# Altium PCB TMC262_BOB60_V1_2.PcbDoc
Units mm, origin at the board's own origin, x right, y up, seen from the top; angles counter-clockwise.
Board outline 38.1 x 30.48 mm, 4 copper layers (Top, GND, VM, Bottom), stack 0.704 mm thick; 33 components, 31 nets, 107 pads, 150 vias.
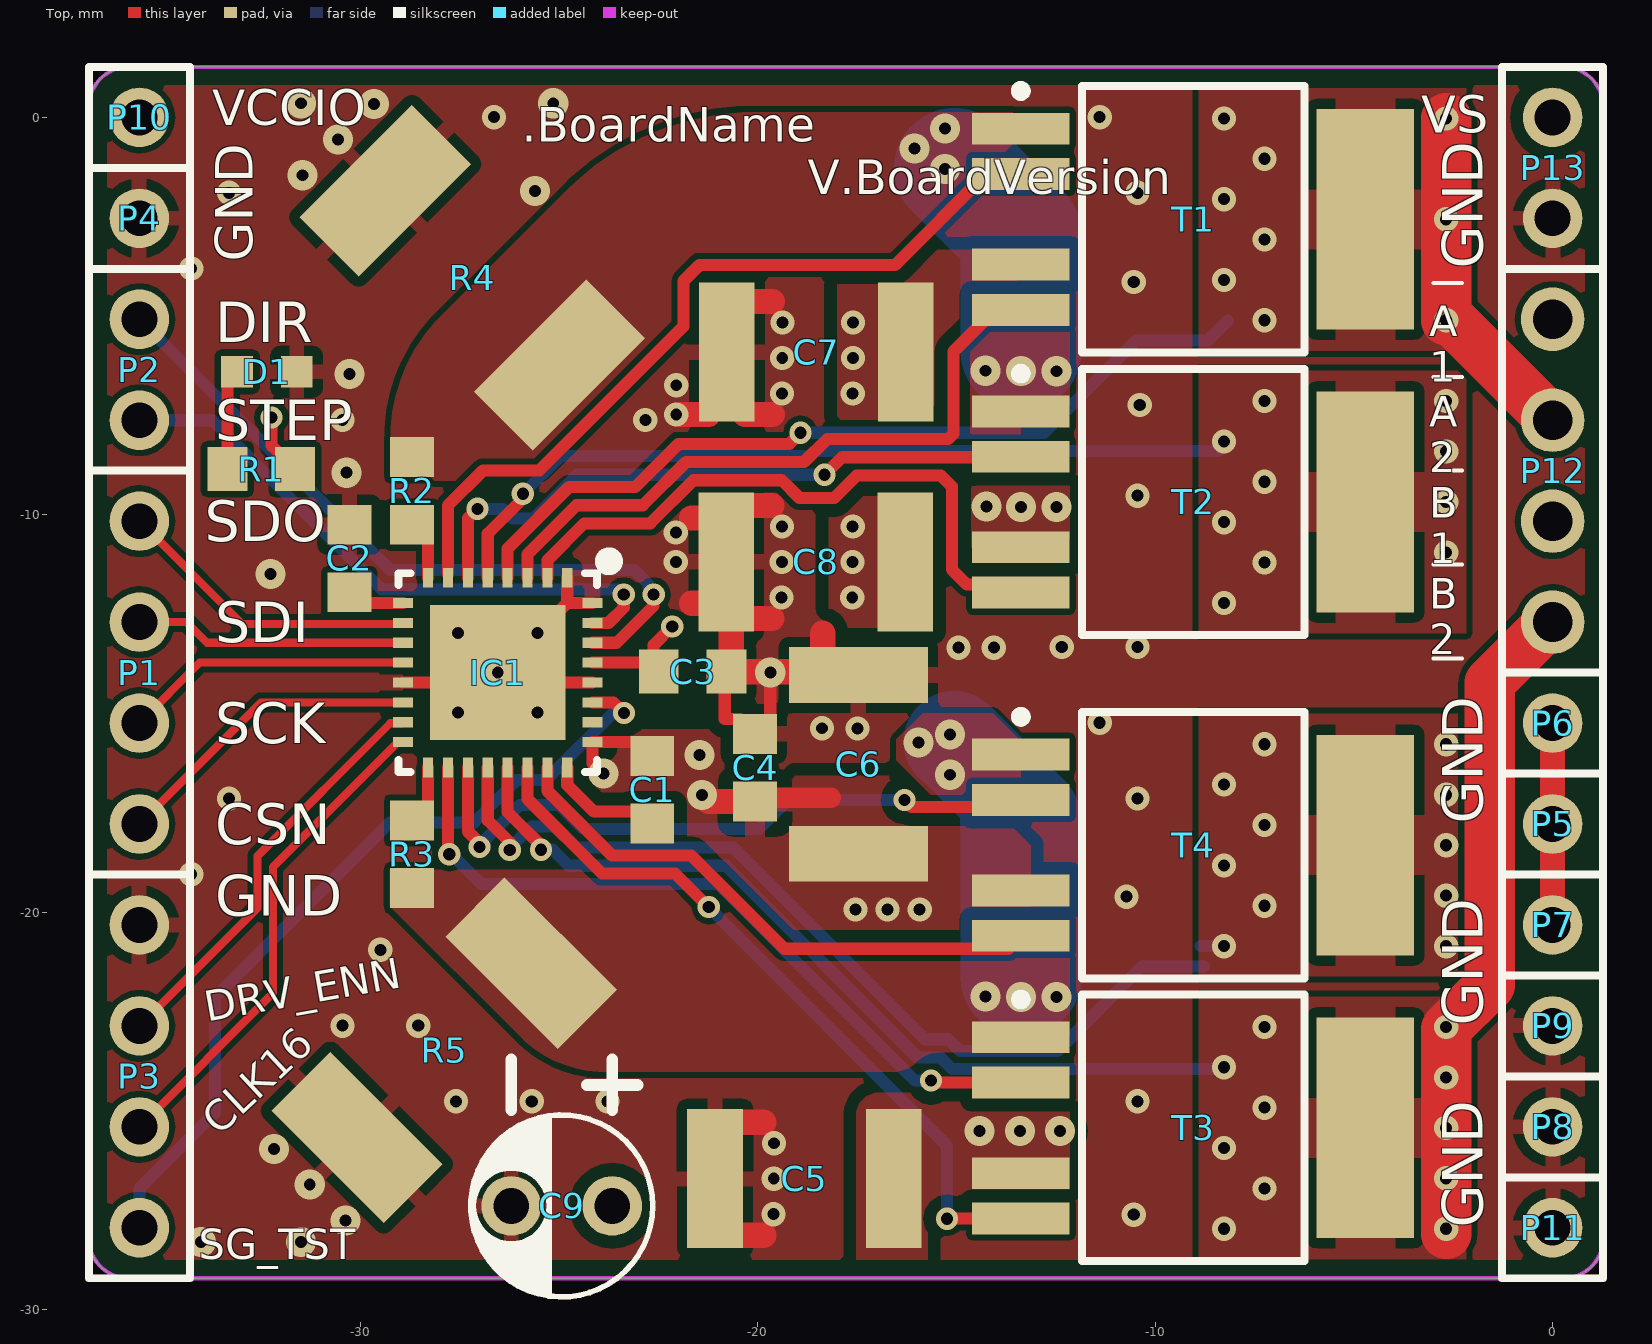
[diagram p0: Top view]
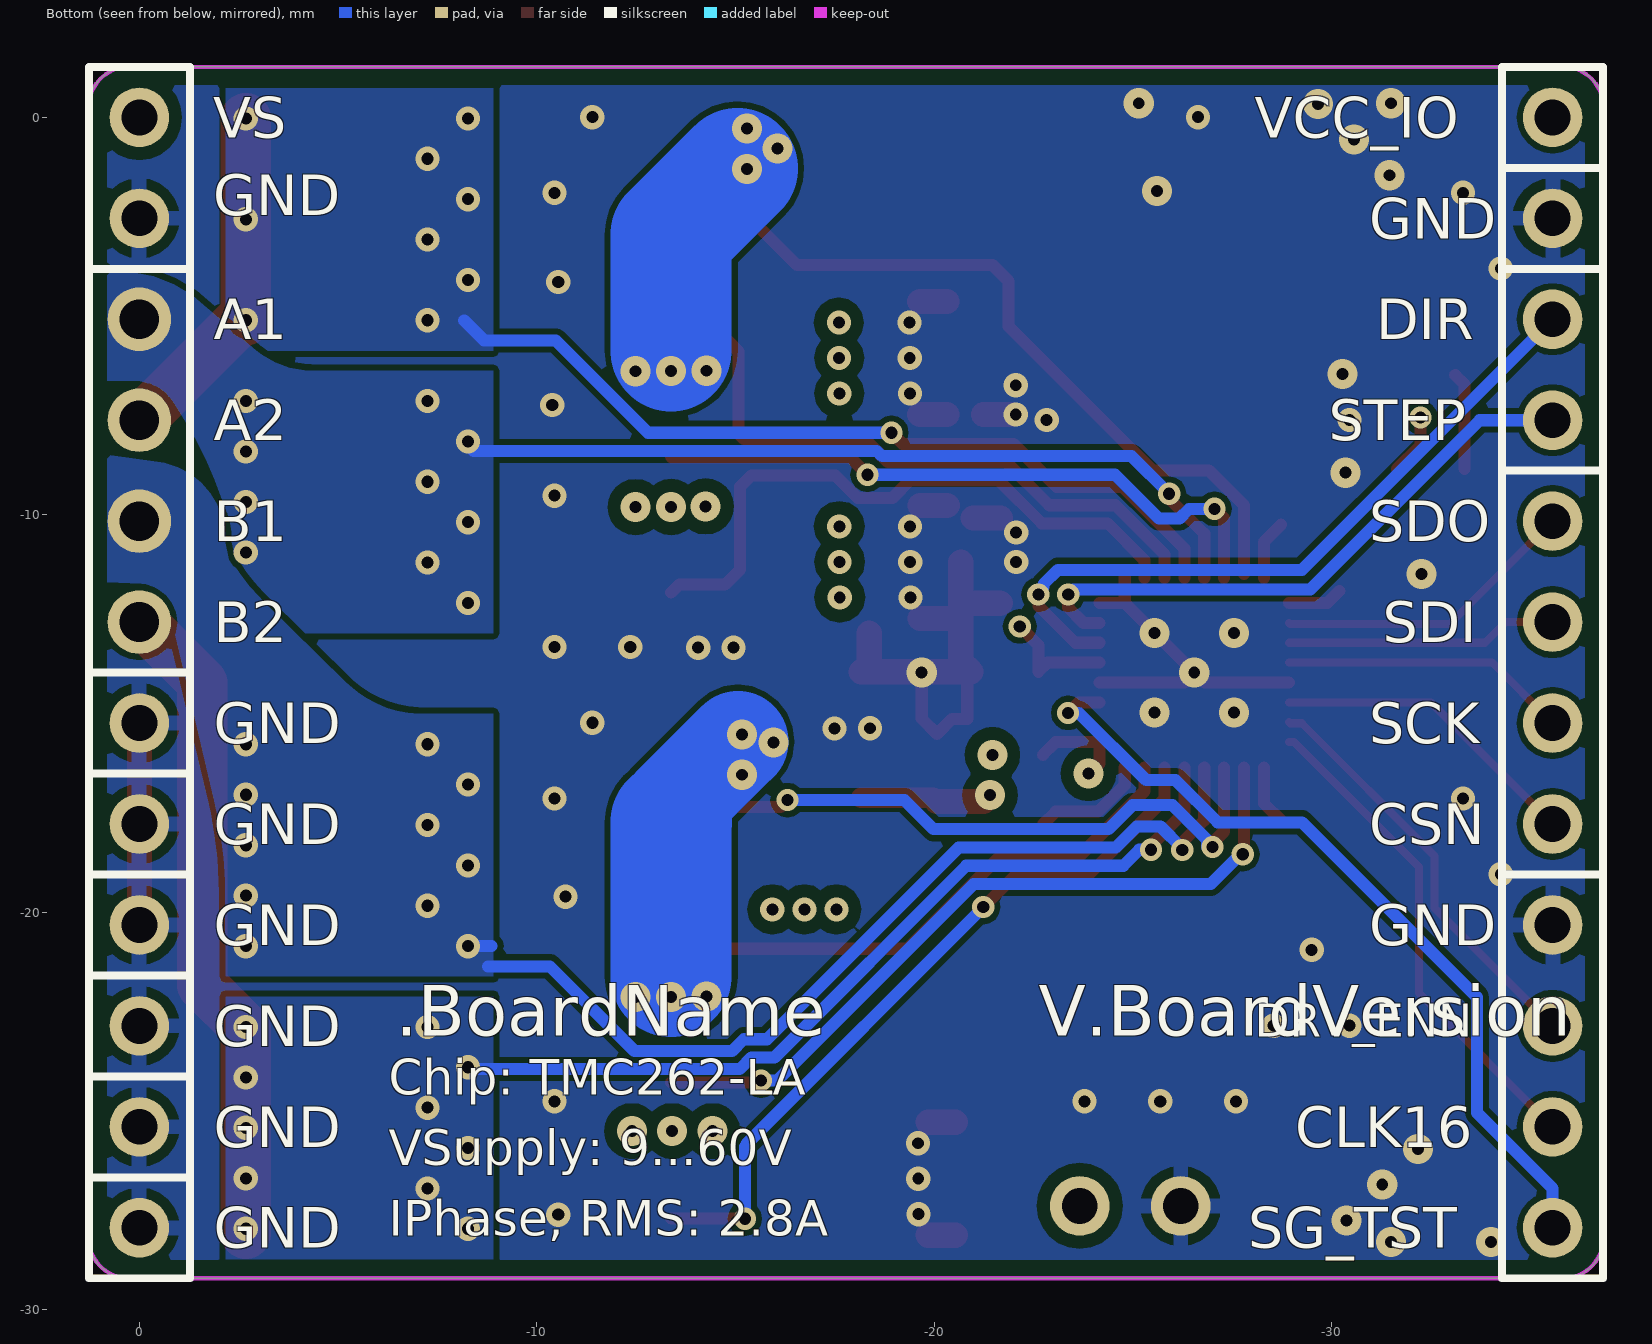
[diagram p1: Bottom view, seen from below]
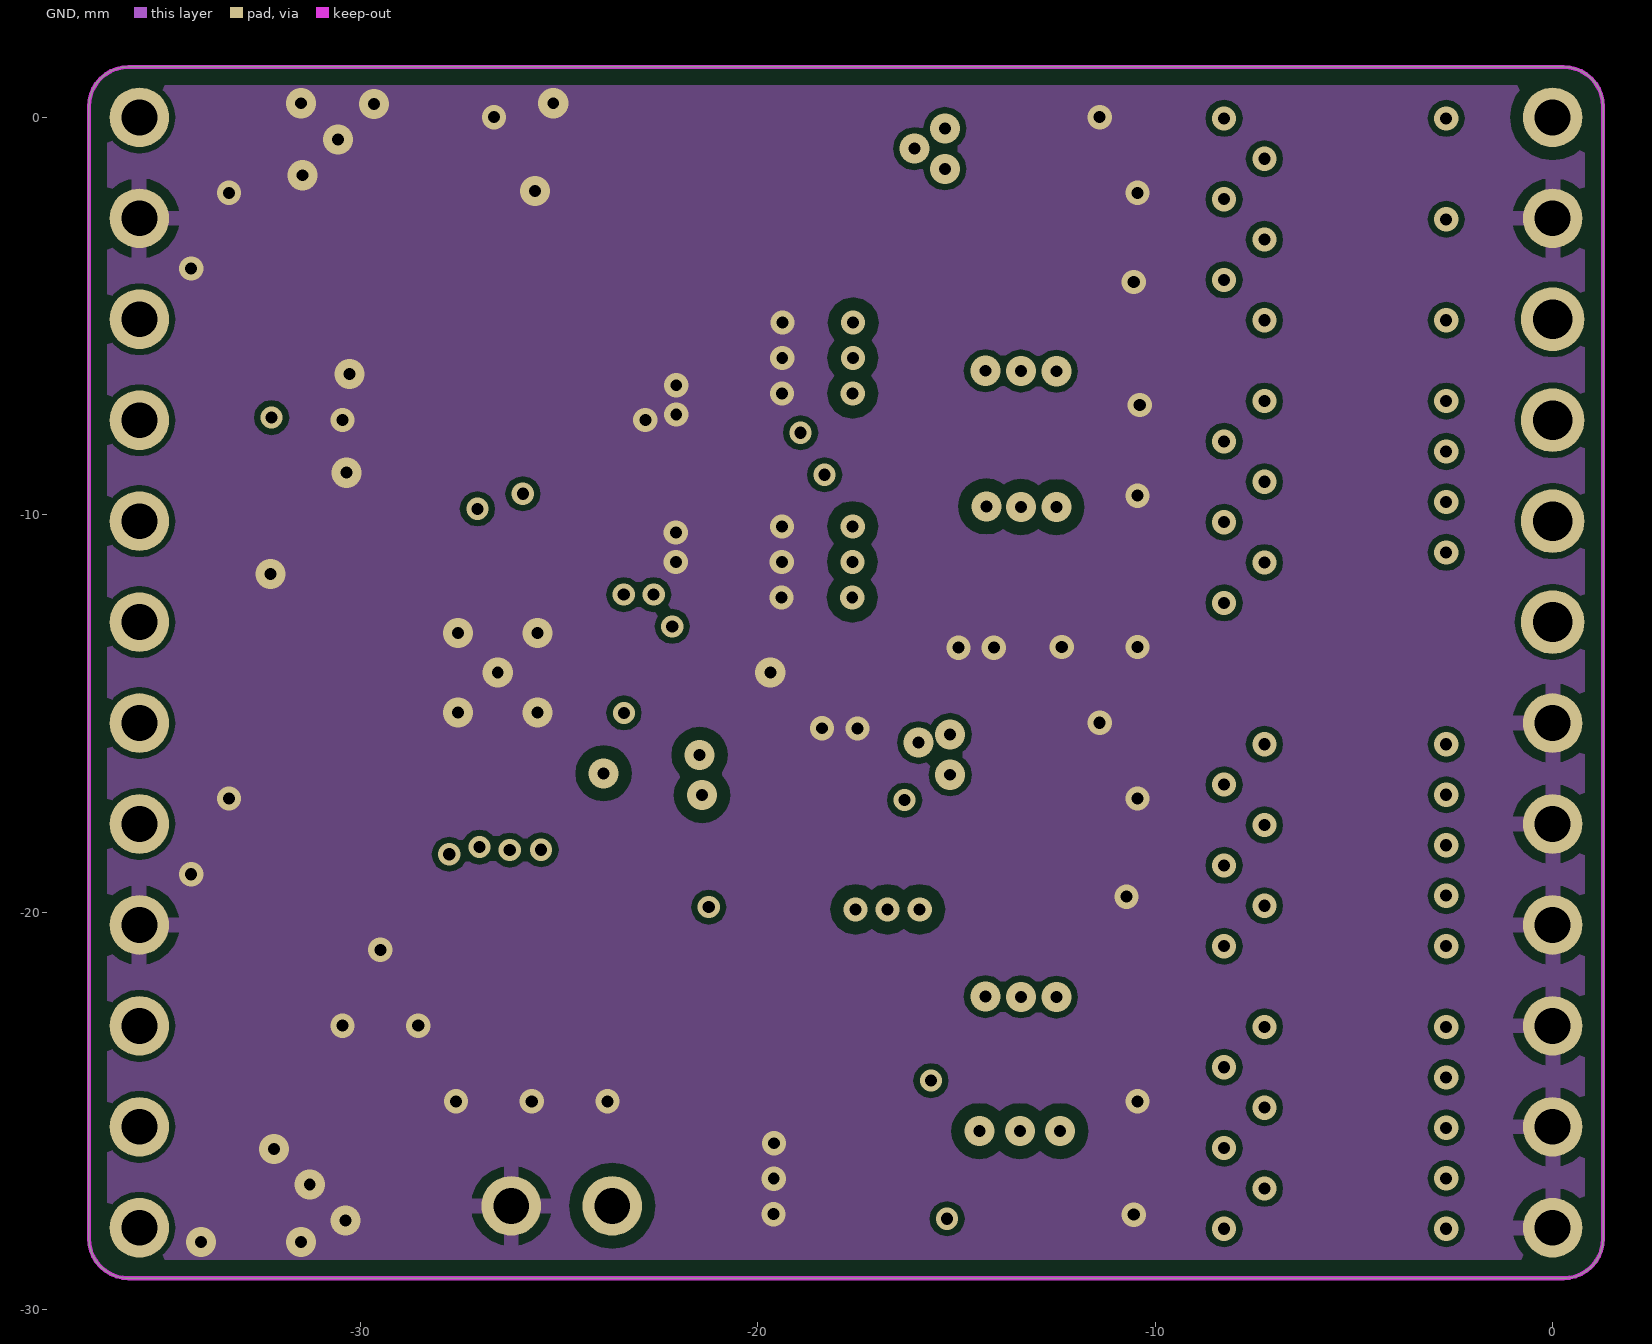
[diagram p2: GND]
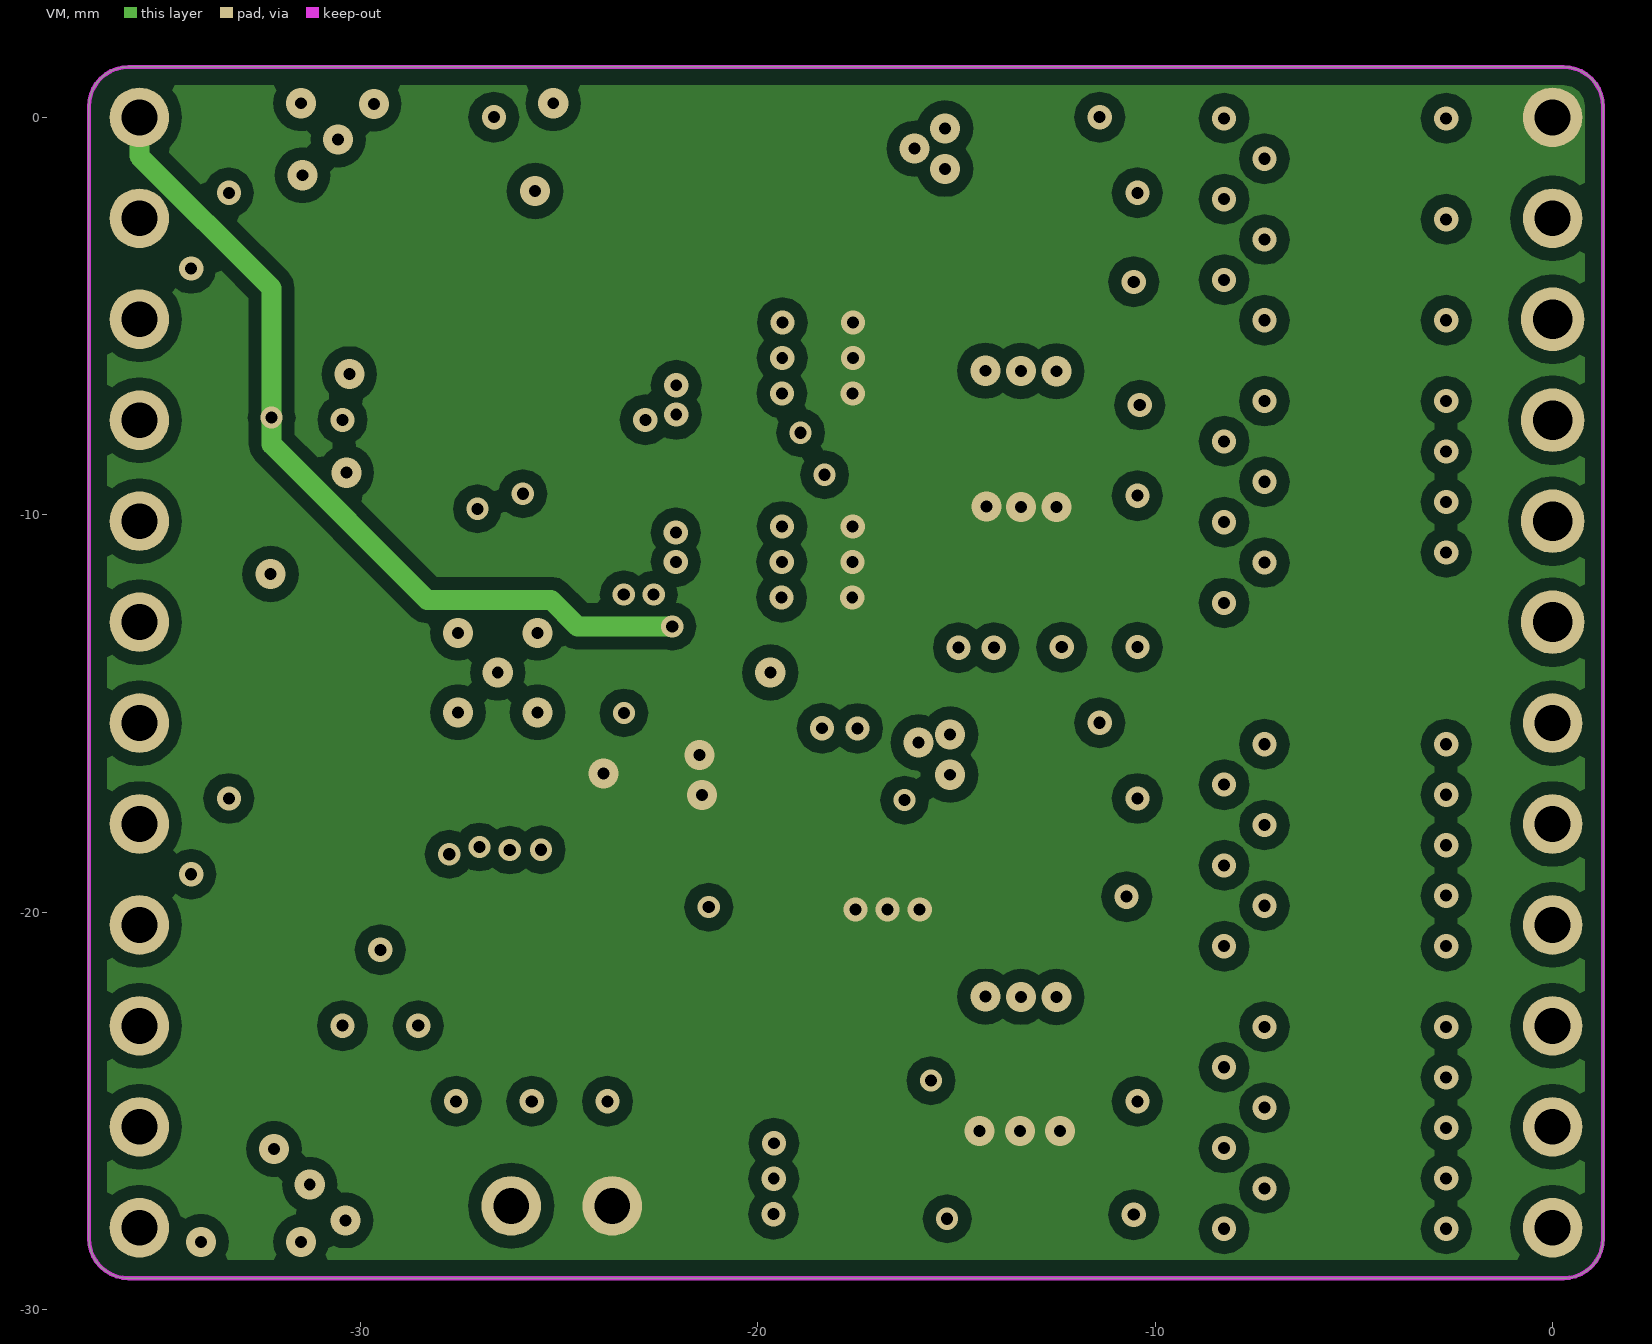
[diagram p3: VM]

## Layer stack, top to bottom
Top Solder: solder mask 0.0102, Solder Resist, Dk 3.5
Top: signal copper 0.035
Dielectric 1: core 0.2, FR-4, Dk 4.8
GND: signal copper 0.0175
Dielectric 2: prepreg 0.127, FR-4, Dk 4.2
VM: signal copper 0.0356
Dielectric4: core 0.254, FR-4, Dk 4.2
Bottom: signal copper 0.035
Bottom Solder: solder mask 0.0102, Solder Resist, Dk 3.5

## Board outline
-36.83,-28.21 -36.83,0.27 cw(c-35.83,0.27) -35.83,1.27 0.27,1.27 cw(c0.27,0.27) 1.27,0.27 1.27,-28.21 cw(c0.27,-28.21) 0.27,-29.21 -35.83,-29.21 cw(c-35.83,-28.21)

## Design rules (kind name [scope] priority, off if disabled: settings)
Clearance BoardOutlineClearance [OnLayer('Keep-Out Layer')] p1: gap=0.4 ignorepadtopadclearanceinfootprint=FALSE except(0: Arc-Hole Track-Hole SMDPad-Hole THPad-Hole Via-Hole Fill-Hole Poly-Hole Region-Hole Text-Hole)
Clearance VM_Clearance [InNet('VM') vs not (InComponent('Q1') or InComponent('Q2') or InComponent('Q3') or InComponent('Q4'))] p2: gap=0.323 ignorepadtopadclearanceinfootprint=TRUE except(0: Arc-Hole Track-Hole SMDPad-Hole THPad-Hole Via-Hole Fill-Hole Poly-Hole Region-Hole Text-Hole)
Clearance "Fiducial Clearance" [HasFootprint('FIDUCIAL_40MIL')] p3: gap=0.66 ignorepadtopadclearanceinfootprint=FALSE except(0: Arc-Hole Track-Hole SMDPad-Hole THPad-Hole Via-Hole Fill-Hole Poly-Hole Region-Hole Text-Hole)
Clearance "Mounting Hole Clearance" [(HoleDiameter >= 110) And  IsPad  And ((PadYSize_AllLayers - HoleDiameter)  <=  1)] p4: gap=0.762 ignorepadtopadclearanceinfootprint=FALSE except(0: Arc-Hole Track-Hole SMDPad-Hole THPad-Hole Via-Hole Fill-Hole Poly-Hole Region-Hole Text-Hole)
Clearance [All] p5: gap=0.152 ignorepadtopadclearanceinfootprint=FALSE except(0: Arc-Hole Track-Hole SMDPad-Hole THPad-Hole Via-Hole Fill-Hole Poly-Hole Region-Hole Text-Hole)
ComponentClearance Pinheader2PinheaderClearance [InComponentClass('Pinheader') vs InComponentClass('Pinheader')] p1: gap=0 collisioncheckmode=3 verticalgap=0 showdistances=FALSE
ComponentClearance [All] p2: gap=0.254 collisioncheckmode=3 verticalgap=0.254 showdistances=FALSE
DiffPairsRouting [All] p1 off: maxlimit=0.254 minlimit=0.191 mostfreqgap=0.254 toplayer_prefgap=0.191 toplayer_minwidth=0.191 toplayer_maxwidth=0.191 toplayer_prefwidth=0.191 midlayer1_prefgap=0.191 midlayer1_minwidth=0.191 midlayer1_maxwidth=0.191 midlayer1_prefwidth=0.191 midlayer2_mingap=0.254 midlayer2_minwidth=0.381 midlayer2_maxwidth=0.381 midlayer2_prefwidth=0.381 bottomlayer_prefgap=0.191 bottomlayer_minwidth=0.191 bottomlayer_maxwidth=0.191 bottomlayer_prefwidth=0.191 maxuncoupledlength=12.7
HoleSize [All] p1: absolutevalues=TRUE maxlimit=2540 minlimit=0.3 maxpercent=80.000 minpercent=20.000
HoleToHoleClearance [All] p1: gap=0.203 allowstackedmicrovias=TRUE
MatchedLengths "SD_CARD MatchedLengths" [InNetClass('SD_CARD')] p1: tolerance=0.254 checknetsindiffpair=FALSE checkdiffpairvsdiffpair=TRUE checkxsignals=TRUE checkothers=TRUE
MinimumAnnularRing MinimumViaAnnualRing [All] p1: minimumring=0.125
MinimumSolderMaskSliver STM32_MinimumSolderMaskSliver [(InComponent('STM1') AND InComponent('STM2')) vs (InComponent('STM1') AND InComponent('STM2'))] p1: minsoldermaskwidth=0.025
MinimumSolderMaskSliver USB_HUB_MinimumSolderMaskSliver [InComponent('USB_HUB')] p2: minsoldermaskwidth=0.025
MinimumSolderMaskSliver [All] p3 off: minsoldermaskwidth=0.038
PasteMaskExpansion TestPadPasteMaskExpansion [HasFootprint('SMD_TP_2X2_ROUND')] p1: expansion=-2
PasteMaskExpansion [All] p2: expansion=0
PlaneConnect VM_PlaneConnect [OnLayer('VM') AND InNet('VM')] p1: planeconnectstyle=Relief reliefexpansion=0.508 reliefentries=4 reliefconductorwidth=0.508 reliefairgap=0.254
PlaneConnect [All] p2: planeconnectstyle=Relief reliefexpansion=0.508 reliefentries=4 reliefconductorwidth=0.254 reliefairgap=0.254
PolygonConnect currentSensePolygonConnect [InNetClass('CurrentSense')] p1: connectstyle=Direct reliefconductorwidth=0.254 reliefentries=4 polygonreliefangle="90 Angle" airgapwidth=0.254
PolygonConnect VSA_C1_ConnectStyle [InNet('VM') AND (inComponent('C1') or HasFootprint('SOT114P991X239-6N') or HasFootprint('CKG45NX7S2A106M500JH'))] p2: connectstyle=Direct reliefconductorwidth=0.508 reliefentries=4 polygonreliefangle="90 Angle" airgapwidth=0.203
PolygonConnect VSAViaConnectStyle [InNet('VM') AND IsVia] p3: connectstyle=Direct reliefconductorwidth=0.508 reliefentries=4 polygonreliefangle="90 Angle" airgapwidth=0.203
PolygonConnect VSAConnectStyle [InNet('VM')] p4: thpad.connectstyle=Direct thpad.reliefconductorwidth=0.508 thpad.reliefentries=4 thpad.polygonreliefangle="90 Angle" thpad.airgapwidth=0.381 smdpad.connectstyle=Relief smdpad.reliefconductorwidth=0.508 smdpad.reliefentries=4 smdpad.polygonreliefangle="90 Angle" smdpad.airgapwidth=0.381 via.connectstyle=Direct via.reliefconductorwidth=0.508 via.reliefentries=4 via.polygonreliefangle="90 Angle" via.airgapwidth=0.381
PolygonConnect MotorPhaseConnectStyle [InNetClass('MotorPower')] p5: thpad.connectstyle=Direct thpad.reliefconductorwidth=0.254 thpad.reliefentries=4 thpad.polygonreliefangle="90 Angle" thpad.airgapwidth=0.254 smdpad.connectstyle=Relief smdpad.reliefconductorwidth=1.524 smdpad.reliefentries=4 smdpad.polygonreliefangle="90 Angle" smdpad.airgapwidth=0.254 via.connectstyle=Direct via.reliefconductorwidth=0.254 via.reliefentries=4 via.polygonreliefangle="90 Angle" via.airgapwidth=0.254
PolygonConnect ThermalVias [IsVia] p6: connectstyle=Direct reliefconductorwidth=0.254 reliefentries=4 polygonreliefangle="90 Angle" airgapwidth=0.254
PolygonConnect [All] p7: connectstyle=Relief reliefconductorwidth=0.381 reliefentries=4 polygonreliefangle="90 Angle" airgapwidth=0.254
RoutingVias [All] p1: holewidth=0.305 width=0.559 viastyle="Through Hole" minholewidth=0.305 minwidth=0.559 maxholewidth=0.305 maxwidth=1.27
ShortCircuit [All] p1 off: allowed=FALSE
SilkToBoardRegionClearance [All] p1 off:
SilkToSilkClearance [All] p1 off: silktosilkclearance=0.254
SilkToSolderMaskClearance [IsPad] p1 off: minsilkscreentomaskgap=0.254 clearancetoexposedcopper=TRUE
SolderMaskExpansion FiducialSolderMaskExpansion [HasFootprint('FIDUCIAL_40MIL')] p1: expansion=0.66
SolderMaskExpansion [All] p2: expansion=0.102
UnRoutedNet [All] p1 off:
Width VIN_Width [InNetClass('PWR_VIN')] p1: maxlimit=7.62 minlimit=5.08 preferedwidth=5.334
Width Other_Width [All] p2: maxlimit=2540 minlimit=0.203 preferedwidth=0.3 minimp=50.000000 maximp=50.000000 favimp=50.000000
18 further rules are at their usual default settings.

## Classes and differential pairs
net class MotorPower: A1 A2 B1 B2
net class CurrentSense: SRA SRB
differential pair class USB_DIFF: STM_USB STM_USB_D
component class Pinheader: P1 P2 P3 P4 P5 P6 P7 P8 P9 P10 P11 P12 P13

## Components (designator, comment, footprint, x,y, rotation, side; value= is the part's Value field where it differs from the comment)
C1 "220nF/16V/10%" C0603 -22.657,-16.916 r270 top
C2 "470nF/16V/10%" C0603 -30.275,-11.098 r90 top
C3 "100nF/16V/10%" C0603 -21.639,-13.945 r0 top
C4 "100nF/100V/10%" C0603 -20.069,-16.363 r270 top
C5 "10uF/100V/20%" CKG45NX7S2A106M500JH -18.825,-26.703 r0 top
C6 "10uF/100V/20%" CKG45NX7S2A106M500JH -17.47,-16.28 r270 top
C7 "10uF/100V/20%" CKG45NX7S2A106M500JH -18.526,-5.906 r0 top
C8 "10uF/100V/20%" CKG45NX7S2A106M500JH -18.542,-11.185 r0 top
C9 "Cap Pol1" EXT_POL_CAP -23.662,-27.39 r90 top value=TBD
D1 "LED, Blue, SMD, 20mA, 2.8V, 465 nm" LED_0603 -32.352,-6.402 r0 top
IC1 "TMC262-LA" TMC262_QFN32_0.5_5.0X5.0 -26.543,-13.97 r180 top
P1 "SPI" 4_PIN_THT -35.56,-17.78 r0 top
P2 "STEP/DIR" 2_PIN_THT -35.56,-7.62 r0 top
P3 "MISC" 4_PIN_THT -35.56,-27.94 r0 top
P4 "GND" TH_PIN -35.56,-2.54 r90 top
P5 "GND" TH_PIN 0,-17.78 r0 top
P6 "GND" TH_PIN 0,-15.24 r0 top
P7 "GND" TH_PIN 0,-20.32 r0 top
P8 "GND" TH_PIN 0,-25.4 r0 top
P9 "GND" TH_PIN 0,-22.86 r0 top
P10 "GND" TH_PIN -35.56,0 r90 top
P11 "GND" TH_PIN 0,-27.94 r0 top
P12 "MAB" 4_PIN_THT_1mm_hole 0,-5.08 r180 top
P13 "VM" 2_PIN_THT 0,-2.54 r0 top
R1 "1k" R0603 -32.496,-8.848 r180 top
R2 "10R / 1%" R0603 -28.702,-9.398 r270 top
R3 "10R / 1%" R0603 -28.702,-18.542 r90 top
R4 ".075R / 2W / 1%" R2512 -27.181,-4.038 r315 top
R5 ".075R / 2W / 1%" R2512 -27.894,-23.476 r45 top
T1 "AOD603A" SOT114P991X239-6N -9.046,-2.565 r0 top
T2 "AOD603A" SOT114P991X239-6N -9.046,-9.677 r0 top
T3 "AOD603A" SOT114P991X239-6N -9.046,-25.425 r0 top
T4 "AOD603A" SOT114P991X239-6N -9.046,-18.313 r0 top

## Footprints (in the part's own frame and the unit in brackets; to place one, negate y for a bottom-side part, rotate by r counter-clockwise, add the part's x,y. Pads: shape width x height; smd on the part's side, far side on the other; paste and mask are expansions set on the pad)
2_PIN_THT [mm]
  round 1.5 hole 0.9: 1(0,0) 2(0,2.54)
  silkscreen extent -1.27,-1.27 1.27,3.81
4_PIN_THT [mm]
  round 1.5 hole 0.9: 1(0,0) 2(0,2.54) 3(0,5.08) 4(0,7.62)
  silkscreen extent -1.27,-1.27 1.27,8.89
4_PIN_THT_1mm_hole [mm]
  round 1.6 hole 1: 1(0,0) 2(0,2.54) 3(0,5.08) 4(0,7.62)
  silkscreen extent -1.27,-1.27 1.27,8.89
C0603 [mm] "0603 ceramic capacitor"
  rect 1x1.1 smd: 1(-0.85,0) 2(0.85,0)
  body extent -0.8,-0.4 0.8,0.4, height 0.8
CKG45NX7S2A106M500JH [mm] "1812 STACKED capacitor"
  rect 1.4x3.5 smd: 1(-2.25,0) 2(2.25,0)
  body extent -2.5,-1.6 2.5,1.6, height 3.35
EXT_POL_CAP [mm]
  round 1.5 hole 0.9: 1(0,0) 2(0,2.54)
  silkscreen extent -2.29,-1.02 3.68,3.56
LED_0603 [mm]
  rect 0.8x0.8 smd: 1(-0.75,0) 2(0.75,0)
  body extent -0.8,-0.38 0.85,0.35, height 0.68
R0603 [mm] "0603 resistor"
  rect 1x1.1 smd: 1(-0.85,0) 2(0.85,0)
  body extent -0.8,-0.4 0.8,0.4, height 0.45
R2512 [mm] "2512 resistor"
  rect 2.1x4 smd: 1(-3.1,0) 2(3.1,0)
  body extent -3.2,-1.6 3.2,1.6, height 0.59
SOT114P991X239-6N [mm] "SOT223, 6-Leads, Body 6,54x9,91mm (avg), Pitch 1,14mm, IPC Medium Density"
  rect 2.45x0.8 smd: 1(-4.335,2.28) 2(-4.335,1.14) 3(-4.335,-1.14) 4(-4.335,-2.28)
  rect 2.45x5.55 smd: 5(4.335,0)
  silkscreen extent -4.46,-3.35 2.8,3.35, body extent -4.8,-3.25 5.1,3.25, height 2.3
TH_PIN [mm]
  round 1.5 hole 0.9: 1(0,0)
  silkscreen extent -1.27,-1.27 1.27,1.27
TMC262_QFN32_0.5_5.0X5.0 [mm]
  rect 0.254x0.5 smd mask+0.046: 1(-1.75,-2.385) 2(-1.25,-2.385) 3(-0.75,-2.385) 4(-0.25,-2.385) 5(0.25,-2.385) 6(0.75,-2.385) 7(1.25,-2.385) 8(1.75,-2.385) 17(1.75,2.385) 18(1.25,2.385) 19(0.75,2.385) 20(0.25,2.385) 21(-0.25,2.385) 22(-0.75,2.385) 23(-1.25,2.385) 24(-1.75,2.385)
  rect 0.5x0.254 smd mask+0.046: 9(2.385,-1.75) 10(2.385,-1.25) 11(2.385,-0.75) 12(2.385,-0.25) 13(2.385,0.25) 14(2.385,0.75) 15(2.385,1.25) 16(2.385,1.75) 25(-2.385,1.75) 26(-2.385,1.25) 27(-2.385,0.75) 28(-2.385,0.25) 29(-2.385,-0.25) 30(-2.385,-0.75) 31(-2.385,-1.25) 32(-2.385,-1.75)
  rect 3.4x3.4 smd paste-254: 33(0,0)
  silkscreen extent -2.9,-2.9 2.5,2.5, body extent -2.5,-2.5 2.5,2.5, height 0.9

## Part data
C1: library part Capacitor, "Ceramic capacitor", Capacitance=220nF, MPN=MC0603B224K160CT, VoltageRating=16V
C2: library part Capacitor, "Ceramic capacitor", Capacitance=470nF, MPN=MC0603X474K160CT, VoltageRating=16V
C3: library part Capacitor, "Ceramic capacitor", Capacitance=100nF, MPN=MC0603B104K160CT, VoltageRating=16V
C4: library part "0.1 µF, 100 V, ± 10%, X7R, GRM Series", "SMD Multilayer Ceramic Capacitor, 0603 [1608 Metric], 0.1 µF, 100 V, ± 10%, X7R, GRM Series", Capacitance=100nF, MPN=GRM188R72A104KA35D, VoltageRating=100V
C5 C6 C7 C8: library part "10 µF, 100 V, ± 20%, X7S, CKG Series", "SMD Multilayer Ceramic Capacitor, 1812 [4532 Metric], 10 µF, 100 V, ± 20%, X7S, CKG Series", Capacitance=10uF, MPN=CKG45NX7S2A106M500JH, VoltageRating=100V
C9: "Polarized Capacitor (Radial)"
D1: Colour=Blue, Current rating=20mA, MPN=LTST-C191TBKT-5A
IC1: "Energy saving high resolution microstepping two phase stepper driver with Step/Dir, SPI, up to 60V, QFN32(5x5)", Manufacturer=TRINAMIC
P1 P3: library part "Header 4", "Header, 4-Pin"
P2 P13: library part "Header 2", "Header, 2-Pin"
P4 P5 P6 P7 P8 P9 P10 P11: library part PIN
P12: library part "Wire-To-Board Connector, 2.5 mm, 4 Contacts, Header, EH Series, Through Hole, 1 Rows", "Wire-To-Board Connector, 2.5 mm, 4 Contacts, Header, EH Series, Through Hole, 1 Rows", MPN=B4B-EH-A
R1: library part "1 kohm, 50 V, 0603 [1608 Metric], 63 mW, ± 1%, MC Series", "1 kohm, 50 V, 0603 [1608 Metric], 63 mW, ± 1%, MC Series", MPN=MC0063W060311K, PowerRating=63mW, Temp coefficient=*ppm, VoltageRating=50V
R2 R3: library part ".05 OHM 2W 1% Current Sense Resistor", "SMD Chip Resistor, Thick Film, 10 ohm, 50 V, 0603 [1608 Metric], 100 mW, ± 1%, MCWR Series", MPN=MCWR06X10R0FTL, PowerRating=100mW, Resistance=10R
R4 R5: library part ".075 OHM 2W 1% Current Sense Resistor", "SMD Current Sense Resistor, 0.075 ohm, 2 W, 2512 [6432 Metric], ± 1%, TLR Series", MPN=TLR3A20WR075FTDG, PowerRating=2W, Resistance=.075R
T1 T2 T3 T4: "Transistor: N/P-MOSFET; unipolar; complementary; -60/60V; TO252-4"

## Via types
v1: diameter 0.61, hole 0.305, Top to Bottom, tented both sides, 45 vias
v2: diameter 0.757, hole 0.3, Top to Bottom, tented both sides, 41 vias
v3: diameter 0.61, hole 0.3, Top to Bottom, tented both sides, 26 vias
v4: diameter 0.612, hole 0.305, Top to Bottom, tented both sides, 21 vias
v5: diameter 0.559, hole 0.305, Top to Bottom, tented both sides, 17 vias

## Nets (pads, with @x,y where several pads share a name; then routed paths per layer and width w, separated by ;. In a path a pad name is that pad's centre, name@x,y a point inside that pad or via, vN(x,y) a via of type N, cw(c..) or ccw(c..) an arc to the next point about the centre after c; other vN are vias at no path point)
A1: IC1.5 P12.1 T2.5 | length 20.7
  Top w0.305: IC1.5 -26.793,-10.478 -25.911,-9.596 v5(-25.911,-9.469)
  Bottom w0.305: v5(-25.911,-9.469) -24.96,-8.518 -18.681,-8.518 -18.554,-8.391 v1@-8.412,-8.391 ; v1@-8.386,-8.366 v1@-8.174,-8.153
  other v1: -8.267,-12.217 -7.251,-11.201 -2.679,-10.947 -8.267,-10.185 -2.679,-9.677 -7.251,-9.169 -2.679,-8.407 -8.267,-8.153 -7.251,-7.137 -2.679,-7.137
A2: IC1.4 P12.2 T1.5 | length 30.2
  Top w0.305: IC1.4 -26.293,-10.846 -24.748,-9.301 -23.083,-9.301 -21.997,-8.216 -19.205,-8.216 v5(-18.923,-7.934)
  Top w1.27: v1(-2.679,-0.025) v1(-2.679,-5.105) -2.679,-4.961 P12.2@0,-7.64
  Bottom w0.305: v5(-18.923,-7.934) -12.798,-7.934 -10.477,-5.613 -8.676,-5.613 -8.174,-5.111
  other v1: -7.251,-5.105 -8.267,-4.089 -7.251,-3.073 -2.679,-2.565 -8.267,-2.057 -7.251,-1.041 -8.267,-0.025
B1: IC1.20 P12.3 T4.5 | length 23.9
  Top w0.305: IC1.20 -26.793,-17.686 -26.241,-18.237 v5(-26.241,-18.435)
  Bottom w0.305: v5(-26.241,-18.435) -26.241,-18.39 -25.696,-17.844 -25.097,-17.844 -24.568,-18.373 -20.614,-18.373 -15.791,-23.196 -15.21,-23.196 -14.916,-23.491 -12.456,-23.491 -10.327,-21.361 -8.775,-21.361 ; -8.865,-20.853 v1(-8.267,-20.853)
  other v1: -2.679,-20.853 -7.251,-19.837 -2.679,-19.583 -8.267,-18.821 -2.679,-18.313 -7.251,-17.805 -2.679,-17.043 -8.267,-16.789 -7.251,-15.773 -2.679,-15.773
B2: IC1.21 P12.4 T3.5 | length 38.4
  Top w0.305: IC1.21 -26.293,-17.481 -25.454,-18.32 v5(-25.454,-18.429)
  Top w1.27: v1@-2.679,-28.092 -2.679,-22.932 -1.587,-21.84 -1.587,-14.227 P12.4@0,-12.64
  Bottom w0.305: v5(-25.454,-18.429) -25.16,-18.429 -24.758,-18.831 -20.803,-18.831 -15.98,-23.653 -15.4,-23.653 -15.105,-23.948 v1@-8.314,-23.948 ; v1@-8.273,-23.907 v1(-8.267,-23.901)
  other v1: -8.267,-27.965 -2.679,-27.965 -7.251,-26.949 -2.679,-26.695 -8.267,-25.933 -2.679,-25.425 -7.251,-24.917 -2.679,-24.155 -7.251,-22.885 -2.679,-22.885
CLK16: IC1.16 P3.2 | length 12.5
  Top w0.203: P3.2 -32.194,-22.034 -32.194,-18.863 -29.051,-15.72 IC1.16
CSN: IC1.14 P1.1 | length 7.9
  Top w0.203: P1.1 -32.5,-14.72 IC1.14
DIR: IC1.30 P2.2 | length 18.1
  Top w0.305: IC1.30 -23.552,-13.22 -22.619,-12.288 v5(-22.619,-12.009)
  Bottom w0.305: P2.2 -29.256,-11.384 -23.112,-11.384 -22.746,-11.75 -22.746,-11.813 -22.619,-11.94 v5(-22.619,-12.009)
DRV_ENN: IC1.15 P3.3 | length 10.6
  Top w0.203: P3.3 -32.59,-19.89 -32.59,-18.589 -29.247,-15.245 -28.954,-15.245 IC1.15
GND: C2.2 C3.2 C4.1 C5.1 C6.1 C7.1 C8.1 C9.2 D1.2 IC1.1 IC1.13 IC1.28 IC1.32 IC1.33 P3.4 P4.1 P5.1 P6.1 P7.1 P8.1 P9.1 P11.1 P13.1 R4.1 R5.1 | length 30.5
  Top w0.305: IC1.13 -26.793,-14.22 v2(-26.543,-13.97) ; IC1.1 -24.793,-12.22 ; IC1.28 -26.293,-14.22 v2(-26.543,-13.97) ; IC1.32 -24.793,-12.22 ; C3.2@-20.92,-13.95 -20.832,-14.038 -20.832,-15.135 -20.447,-15.135 C4.1 -19.685,-15.129 v2(-19.685,-13.97) ; v2(-26.543,-13.97) -24.793,-12.22
  Top w0.635: v3@-21.929,-7.477 C7.1@-21.243,-7.477 ; -21.668,-10.079 C8.1@-20.982,-10.079 ; -21.662,-12.227 C8.1@-20.976,-12.227 ; C3.2 C3.2@-20.92,-13.945 ; C8.1@-20.665,-11.185 -20.665,-13.689 C3.2@-20.92,-13.945 ; C5.1@-20.534,-28.127 -19.848,-28.127 ; C5.1@-20.534,-25.282 -19.848,-25.282 ; C8.1@-20.331,-12.607 -19.645,-12.607 ; C8.1@-20.331,-9.763 -19.645,-9.763 ; C7.1@-20.32,-7.477 -19.634,-7.477 ; C7.1@-20.32,-4.632 -19.634,-4.632 ; v2(-19.685,-13.97) v2@-19.685,-13.95 ; C6.1@-18.366,-13.886 -18.366,-12.982 ; C6.1@-18.161,-13.95 v2@-19.685,-13.95 ; P7.1 P5.1 P6.1 ; C3.2@-20.92,-13.945 -20.92,-13.95 v2@-19.685,-13.95
  other v1: -10.541,-27.61 -10.719,-19.609 -10.389,-7.239 -10.541,-4.14
  other v2: -34.011,-28.295 -31.496,-28.295 -30.374,-27.753 -31.272,-26.855 -32.17,-25.957 -27.543,-14.97 -25.543,-14.97 -27.543,-12.97 -25.543,-12.97 -32.258,-11.49 -30.353,-8.941 -30.277,-6.461 -25.603,-1.854 -31.457,-1.456 -30.559,-0.558 -29.661,0.341 -31.496,0.356 -25.146,0.356
  other v3: -19.605,-27.597 -19.599,-26.704 -19.593,-25.812 -17.49,-15.376 -18.383,-15.37 -14.95,-13.344 -14.061,-13.344 -19.401,-12.077 -22.062,-11.185 -19.395,-11.185 -22.062,-10.448 -19.389,-10.293 -22.052,-7.477 -19.391,-6.947 -22.052,-6.74 -19.385,-6.054 -19.379,-5.162
  other v4: -27.591,-24.758 -25.686,-24.758 -23.781,-24.758 -10.446,-24.758 -30.449,-22.853 -28.544,-22.853 -29.496,-20.948 -34.259,-19.043 -33.306,-17.138 -10.446,-17.138 -11.399,-15.233 -12.351,-13.328 -10.446,-13.328 -10.446,-9.518 -30.449,-7.613 -22.829,-7.613 -34.259,-3.803 -33.306,-1.898 -10.446,-1.898 -26.639,0.007 -11.399,0.007
HA1: IC1.2 T2.4 | length 16.1
  Top w0.305: IC1.2 -25.293,-11.143 -24.366,-10.216 -22.704,-10.216 -21.618,-9.13 -19.393,-9.13 -18.948,-9.575 -18.077,-9.575 -17.512,-9.01 -15.395,-9.01 -15.117,-9.288 -15.117,-11.378 -14.74,-11.755 -13.583,-11.755 T2.4
HA2: IC1.3 T1.4 | length 16.8
  Top w0.305: IC1.3 -25.793,-10.992 -24.559,-9.759 -22.893,-9.759 -21.808,-8.673 -18.836,-8.673 -18.259,-8.096 -15.214,-8.096 -15.077,-7.959 -15.077,-5.889 -14.033,-4.845 T1.4
HB1: IC1.23 T4.4 | length 14.3
  Top w0.305: IC1.23 -25.293,-16.948 -23.67,-18.571 -21.675,-18.571 -19.327,-20.92 -13.695,-20.92 T4.4@-13.381,-20.605
HB2: IC1.22 T3.4 | length 18.7
  Top w0.305: IC1.22 -25.793,-17.149 -23.913,-19.028 -22.078,-19.028 v5(-21.234,-19.872) ; v5(-15.235,-27.713) -15.228,-27.705 T3.4
  Bottom w0.305: v5(-21.234,-19.872) -15.276,-25.83 -15.276,-25.861 -15.235,-25.902 v5(-15.235,-27.713)
LA1: IC1.6 T2.2 | length 16.3
  Top w0.305: IC1.6 -27.291,-11.583 -27.291,-10.087 v5(-27.054,-9.85) ; v5(-18.319,-8.991) -17.881,-8.553 -13.396,-8.553 T2.2
  Bottom w0.305: v5(-27.054,-9.85) -26.414,-9.85 -26.17,-10.094 -25.652,-10.094 -24.549,-8.991 v5(-18.319,-8.991)
LA2: IC1.7 T1.2 | length 20.3
  Top w0.305: IC1.7@-27.793,-11.487 -27.793,-9.763 -26.915,-8.885 -25.496,-8.885 -21.869,-5.258 -21.869,-4.118 -21.464,-3.712 -16.543,-3.712 -14.257,-1.425 T1.2
LB1: IC1.19 T4.2 | length 17
  Top w0.305: IC1.19 -27.293,-17.968 -27.003,-18.257 v5(-27.003,-18.359) ; v5(-16.307,-17.18) -16.131,-17.355 -14.247,-17.355 -14.065,-17.173 T4.2
  Bottom w0.305: v5(-27.003,-18.359) -26.866,-18.359 -26.866,-18.176 -25.996,-17.306 -24.989,-17.306 -24.384,-17.911 -19.984,-17.911 -19.253,-17.18 v5(-16.307,-17.18)
LB2: IC1.18 T3.2 | length 19
  Top w0.305: IC1.18 -27.793,-18.512 v5(-27.763,-18.542) ; v5(-15.642,-24.238) -15.594,-24.285 T3.2
  Bottom w0.305: v5(-27.763,-18.542) -27.704,-18.542 -26.958,-19.288 -20.992,-19.288 -16.043,-24.238 v5(-15.642,-24.238)
NetC1_2: C1.2 IC1.24 | length 2.9
  Top w0.305: IC1.24 -24.793,-16.798 -24.121,-17.47 -23.055,-17.47 C1.2@-22.733,-17.792
NetC2_1: C2.1 IC1.9 | length 1.4
  Top w0.305: C2.1@-30.191,-11.918 -29.889,-12.22 IC1.9
NetD1_1: D1.1 R1.2 | length 2.5
  Top w0.305: R1.2 -33.346,-6.722 D1.1@-33.11,-6.486
NetIC1_8: IC1.8 R2.2 | length 1.5
  Top w0.305: R2.2@-28.727,-10.248 -28.293,-10.682 IC1.8
NetIC1_17: IC1.17 R3.2 | length 1.5
  Top w0.305: R3.2@-28.727,-17.692 -28.293,-17.258 IC1.17
SCK: IC1.12 P1.2 | length 7.3
  Top w0.203: P1.2 -34.04,-13.72 IC1.12
SDI: IC1.11 P1.3 | length 6.8
  Top w0.203: P1.3 -34.38,-12.7 -33.86,-13.22 IC1.11
SDO: IC1.10 P1.4 | length 7.7
  Top w0.203: P1.4 -32.977,-12.743 -28.951,-12.743 IC1.10
SG_TST: IC1.27 P3.1 | length 20.7
  Top w0.305: IC1.27 -23.634,-14.72 v5(-23.368,-14.986)
  Bottom w0.305: P3.1 -35.56,-26.949 -33.655,-25.044 -33.655,-22.139 -29.255,-17.738 -27.132,-17.738 -26.068,-16.674 -25.326,-16.674 -23.638,-14.986 v5(-23.368,-14.986)
SRA: R2.1 R4.2 T1.1 T2.1 | length 5.3
  Bottom w3.048: v2@-15.049,-1.282 -13.391,-2.94 -13.381,-2.95 -13.381,-5.873
  other v2: -13.381,-6.381 -12.488,-6.387 -14.273,-6.375 -15.289,-1.295 -16.051,-0.787 -15.289,-0.279
SRB: R3.1 R5.2 T3.1 T4.1 | length 6.6
  Bottom w2.54: v2@-15.058,-15.702 -13.386,-17.375 -13.386,-17.729
  Bottom w3.048: -13.386,-17.729 -13.381,-17.734 -13.381,-21.621
  other v2: -13.381,-22.129 -12.488,-22.135 -14.273,-22.123 -15.159,-16.541 -15.951,-15.732 -15.159,-15.525
STEP: IC1.31 P2.1 | length 15.3
  Top w0.305: IC1.31 -23.756,-12.72 -23.371,-12.335 v5(-23.371,-12.009)
  Bottom w0.305: P2.1 -33.724,-7.62 -29.462,-11.882 -23.498,-11.882 v5(-23.371,-12.009)
VCC_IO: C3.1 IC1.29 P10.1 R1.1 | length 26.1
  Top w0.305: v5(-32.233,-7.553) -32.233,-8.261 R1.1 ; IC1.29 -22.85,-13.72 -22.62,-13.95 -22.62,-13.276 v5(-22.151,-12.807)
  VM w0.508: P10.1 -35.56,-0.975 -32.233,-4.302 v5(-32.233,-7.553) -32.233,-8.229 -28.317,-12.144 -25.201,-12.144 -24.539,-12.807 v5(-22.151,-12.807)
VM: C1.1 C4.2 C5.2 C6.2 C7.2 C8.2 C9.1 IC1.25 P13.2 T1.3 T2.3 T3.3 T4.3 | length 5.8
  Top w0.305: v2@-23.929,-16.49 -24.158,-16.261 IC1.25 -23.054,-15.72 C1.1@-22.733,-16.041
  Top w0.508: C4.2 -19.977,-17.121 -18.161,-17.121
  Top w0.635: v2(-21.402,-17.052) -21.241,-17.213 C4.2
  other v2: -14.422,-25.508 -13.406,-25.508 -12.39,-25.508 -23.879,-16.505 -21.463,-16.041 -14.249,-9.788 -13.381,-9.801 -12.488,-9.807
  other v3: -17.541,-19.93 -16.733,-19.93 -15.926,-19.93 -17.623,-12.077 -17.617,-11.185 -17.611,-10.293 -17.613,-6.947 -17.607,-6.054 -17.601,-5.162
pads on no net: IC1.26

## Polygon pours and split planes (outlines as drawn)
GND on Bottom "GND_L04_P155" (solid, pour order 155): -36.83,-28.21 -36.83,0.27 cw(c-35.83,0.27) -35.83,1.27 0.27,1.27 cw(c0.27,0.27) 1.27,0.27 1.27,-28.21 cw(c0.27,-28.21) 0.27,-29.21 -35.83,-29.21 cw(c-35.83,-28.21)
B1 on Bottom "B1_L04_P153" (solid, pour order 153): -2.163,-10.635 cw(c-3.118,-10.635) -2.296,-11.122 cw(c-6.746,-8.488) -3.12,-12.174 -5.177,-14.199 cw(c-7.162,-12.181) -7.162,-15.011 -7.417,-15.011 -7.417,-20.574 -2.159,-20.574 -2.159,-19.501 cw(c7.839,-19.501) -1.889,-17.195 -0.723,-12.275 cw(c-0.034,-12.438) -0.063,-11.731 1.27,-11.677 1.27,-8.422 -0.444,-8.663 ccw(c-0.165,-10.641)
B1 on Bottom "B1_L04_P151" (solid, pour order 151): -8.902,-15.011 -8.902,-21.615 -2.171,-21.615 -2.171,-15.011
A1 on Bottom "A1_L04_P149" (solid, pour order 149): 1.27,-3.886 0.541,-3.886 ccw(c0.54,-7.714) 0.431,-3.888 ccw(c0.521,-7.038) -1.537,-4.651 -2.933,-5.855 cw(c-4.333,-4.232) -4.333,-6.375 -4.75,-6.375 -4.75,-9.931 -2.193,-9.931 cw(c7.719,-13.016) -1.27,-7.823 -0.867,-7.181 cw(c0.129,-7.805) 0.128,-6.63 1.27,-6.629
B2 on Bottom "B2_L04_P152" (solid, pour order 152): -8.902,-22.123 -8.902,-28.727 -2.171,-28.727 -2.171,-22.123
A1 on Bottom "A1_L04_P154" (solid, pour order 154): -8.902,-6.375 -8.902,-12.979 -2.171,-12.979 -2.171,-6.375
A2 on Bottom "A2_L04_P150" (solid, pour order 150): -8.902,0.737 -8.902,-5.867 -2.171,-5.867 -2.171,0.737
SRB on Top "SRB_L01_P133" (solid, pour order 133): -14.07,-14.994 -15.854,-14.994 -16.513,-15.653 -16.513,-16.181 -15.654,-17.041 -13.753,-17.041 -13.381,-16.668 -13.381,-15.683
SRA on Top "SRA_L01_P144" (solid, pour order 144): -13.589,0.127 -20.064,0.127 ccw(c-20.064,-6.577) -24.804,-1.836 -27.975,-5.007 ccw(c-24.932,-8.05) -29.235,-8.051 -28.142,-9.144 -26.193,-9.144 -20.996,-3.947 -16.856,-3.947 -13.589,-0.68
SRA on Top "SRA_L01_P136" (solid, pour order 136): -13.381,-7.397 -13.381,-8.537 -14.651,-8.537 -14.651,-5.463 -14.299,-5.111 -12.283,-5.111 -12.156,-5.238 -12.156,-7.27
VM on Top "VM_L01_P137" (solid, pour order 137): -13.381,-3.333 -18.006,-3.333 -18.006,-7.934 -16.256,-7.934 -13.381,-5.059
VM on Top "VM_L01_P134" (solid, pour order 134): -13.381,-10.817 -13.39,-10.826 -14.651,-10.826 -14.651,-8.667 -14.524,-8.54 -12.156,-8.54 -12.156,-10.617 -12.365,-10.826
VM on Top "VM_L01_P138" (solid, pour order 138): -12.165,-27.411 -15.723,-27.423 -15.723,-29.21 -17.524,-29.21 -17.524,-25.128 cw(c-16.942,-25.128) -16.942,-24.546 -12.156,-24.546 -12.156,-27.401
VM on Top "VM_L01_P139" (solid, pour order 139): -13.853,-16.57 -19.259,-16.57 -19.788,-16.041 -20.756,-16.041 -20.756,-15.576 -20.939,-15.393 -24.251,-15.393 -24.251,-16.887 -22.408,-18.73 -20.818,-18.73 -18.688,-20.859 -13.127,-20.859 -13.127,-18.319 -13.853,-17.594
SRB on Top "SRB_L01_P145" (solid, pour order 145): -12.537,-23.526 -12.156,-23.145 -12.156,-20.986 -13.299,-19.843 -20.847,-19.843 -21.765,-18.926 -29.256,-18.926 -29.256,-19.843 -25.948,-23.151 ccw(c-23.871,-21.074) -23.871,-24.012 -16.581,-24.012 ccw(c-16.581,-23.213) -16.016,-23.778 cw(c-15.409,-24.384) -15.409,-23.526
VM on Top "VM_L01_P135" (solid, pour order 135): -16.347,-9.534 -17.744,-9.534 -18.219,-10.009 -18.219,-12.361 -17.744,-12.836 -15.966,-12.836
GND on Top "GND_L01_P146" (solid, pour order 146): -36.83,-28.21 -36.83,0.27 cw(c-35.83,0.27) -35.83,1.27 0.27,1.27 cw(c0.27,0.27) 1.27,0.27 1.27,-28.21 cw(c0.27,-28.21) 0.27,-29.21 -35.83,-29.21 cw(c-35.83,-28.21)
A2 on Top "A2_L01_P140" (solid, pour order 140): -8.902,0.737 -8.902,-5.867 -2.171,-5.867 -2.171,0.737
A1 on Top "A1_L01_P142" (solid, pour order 142): -8.902,-6.375 -8.902,-12.979 -2.171,-12.979 -2.171,-6.375
B1 on Top "B1_L01_P141" (solid, pour order 141): -8.902,-15.011 -8.902,-21.615 -2.171,-21.615 -2.171,-15.011
B2 on Top "B2_L01_P143" (solid, pour order 143): -8.902,-22.123 -8.902,-28.727 -2.171,-28.727 -2.171,-22.123
VM on VM "VM_L03_P148" (solid, pour order 148): -36.83,-28.21 -36.83,0.27 cw(c-35.83,0.27) -35.83,1.27 0.27,1.27 cw(c0.27,0.27) 1.27,0.27 1.27,-28.21 cw(c0.27,-28.21) 0.27,-29.21 -35.83,-29.21 cw(c-35.83,-28.21)
GND on GND "GND_L02_P147" (solid, pour order 147): -36.83,-28.21 -36.83,0.27 cw(c-35.83,0.27) -35.83,1.27 0.27,1.27 cw(c0.27,0.27) 1.27,0.27 1.27,-28.21 cw(c0.27,-28.21) 0.27,-29.21 -35.83,-29.21 cw(c-35.83,-28.21)

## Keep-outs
Keep-Out Layer:
  the board outline again, w0.102

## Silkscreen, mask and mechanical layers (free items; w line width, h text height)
Top Overlay:
  lines w0.102: -2.997,-13.614 -2.286,-13.614 ; -2.997,-11.252 -2.286,-11.252 ; -2.997,-8.89 -2.286,-8.89 ; -2.997,-6.528 -2.286,-6.528 ; -2.997,-4.166 -2.286,-4.166
  text "VCCIO" at -33.731,-0.203 h0.89
  text "VS" at -3.302,-0.381 h0.94
  text ".BoardName" at -25.933,-0.619 h0.86
  text "V.BoardVersion" at -18.745,-1.94 h0.86
  text "GND" at -32.705,-3.632 h0.95 r90
  text "GND" at -1.753,-3.81 h1.02 r90
  text "DIR" at -33.655,-5.664 h1.02
  text "STEP" at -33.655,-8.128 h1.02
  text "SDO" at -33.909,-10.668 h1.02
  text "SDI" at -33.655,-13.208 h1.02
  text "A / 1 / A / 2 / B / 1 / B / 2" at -3.099,-13.504 h0.76
  text "SCK" at -33.655,-15.748 h1.02
  text "GND" at -1.753,-17.78 h1.02 r90
  text "CSN" at -33.655,-18.288 h1.02
  text "GND" at -33.655,-20.091 h1.02
  text "DRV_ENN" at -33.858,-22.758 h0.76 r10
  text "GND" at -1.753,-22.86 h1.02 r90
  text "CLK16" at -33.553,-25.654 h0.76 r43
  text "GND" at -1.753,-27.94 h1.02 r90
  text "SG_TST" at -34.068,-28.727 h0.76
Bottom Overlay:
  lines w0.203: -1.27,-13.97 -1.27,-3.81
  text "VCC_IO" at -28.069,-0.508 h1.02
  text "VS" at -1.864,-0.508 h1.02
  text "GND" at -1.864,-2.464 h1.02
  text "GND" at -30.947,-3.048 h1.02
  text "DIR" at -31.116,-5.588 h1.02
  text "A1" at -1.868,-5.588 h1.02
  text "STEP" at -29.931,-8.128 h1.02
  text "A2" at -1.868,-8.128 h1.02
  text "SDO" at -30.947,-10.668 h1.02
  text "B1" at -1.868,-10.668 h1.02
  text "SDI" at -31.285,-13.208 h1.02
  text "B2" at -1.868,-13.208 h1.02
  text "SCK" at -30.947,-15.748 h1.02
  text "GND" at -1.868,-15.748 h1.02
  text "CSN" at -30.947,-18.288 h1.02
  text "GND" at -1.868,-18.288 h1.02
  text "GND" at -30.947,-20.828 h1.02
  text "GND" at -1.868,-20.828 h1.02
  text "V.BoardVersion" at -22.631,-23.114 h1.27
  text ".BoardName" at -6.452,-23.114 h1.27
  text "DRV_ENN" at -28.069,-23.139 h0.84
  text "GND" at -1.868,-23.368 h1.02
  text "Chip: TMC262-LA" at -6.274,-24.892 h1.52
  text "CLK16" at -29.084,-25.908 h1.02
  text "GND" at -1.868,-25.908 h1.02
  text "VSupply: 9...60V" at -6.274,-26.67 h1.52
  text "SG_TST" at -27.9,-28.448 h1.02
  text "IPhase, RMS: 2.8A" at -6.274,-28.448 h1.52
  text "GND" at -1.868,-28.448 h1.02
TopAsm:
  text ".BoardName" at -33.519,-0.356 h1.27
  text ".BoardVersion" at -15.891,-0.483 h1.27

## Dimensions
0.27,-29.21 to 0.27,1.27 on Dimension
-36.83,0.27 to 1.27,0.27 on Dimension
